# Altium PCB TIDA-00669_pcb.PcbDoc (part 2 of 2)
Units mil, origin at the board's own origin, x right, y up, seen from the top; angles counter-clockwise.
Board outline 2510.03 x 1760.03 mil, 2 copper layers (Top Layer, Bottom Layer), stack 62 mil thick; 109 components, 52 nets, 337 pads, 6 vias.
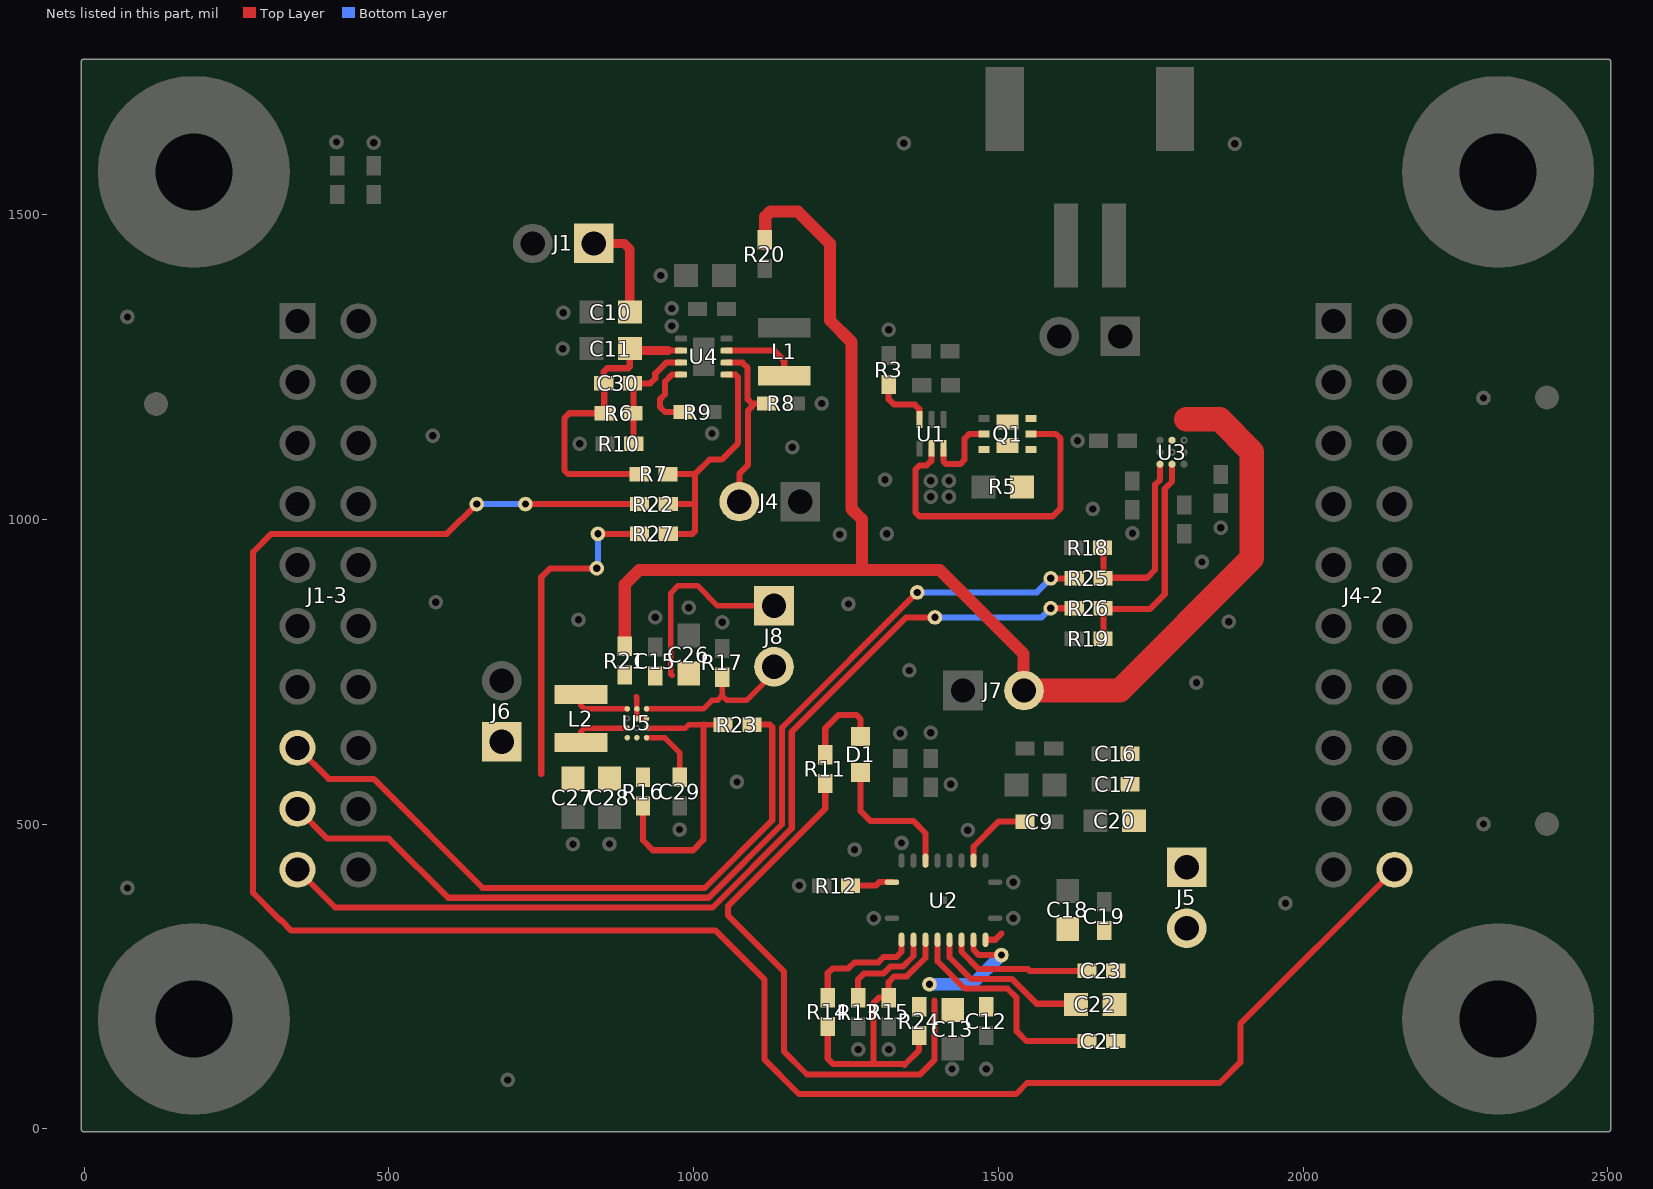
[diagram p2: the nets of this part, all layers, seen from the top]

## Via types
v1: diameter 19.68, hole 7.87, Top Layer to Bottom Layer, 6 vias

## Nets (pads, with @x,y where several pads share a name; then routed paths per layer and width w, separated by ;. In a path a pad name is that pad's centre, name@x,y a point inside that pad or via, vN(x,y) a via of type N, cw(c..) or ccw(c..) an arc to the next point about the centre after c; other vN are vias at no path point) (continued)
NetC9_1: C9.1 U2.3 | length 124.5
  Top Layer w10: U2.3@1459.21,439.96 1459.21,463 1500.15,503.94 C9.1@1543.76,503.94
NetC10_1: C10.1 C11.1 C30.1 J1.1 R6.2 R7.2 U4.2 | length 676.3
  Top Layer w10: C11.1@895.2,1280 895.2,1250.23 892.71,1247.74 858,1247.74 852.38,1242.12 C30.1@852.38,1223 853.38,1222 R6.2@853.38,1174 796,1174 788,1166 788,1080 794,1074 R7.2@910.76,1074 ; 957.7,1276.7 U4.2@979.39,1276.7
  Top Layer w15: J1.1@836.16,1452.58 886.16,1452.58 895.2,1443.54 C10.1@895.2,1340 ; C11.1@895.2,1280 898.49,1276.7 957.7,1276.7
NetC12_1: C12.1 C13.1 pad.0@1387,237 pad.0@1505,285 R11.2 R24.2 U2.18 | length 1116.8
  Top Layer w10: R11.2@1216,566.38 1216,525 1056.63,365.63 1056.63,349.63 1148,258.25 1148,127 1186,89 1371,89 1371.15,88.85 1395,112.7 1395,210 ; U2.18@1459.21,310.04 1459.21,293.79 1468,285 pad.0@1505,285
  Bottom Layer w20: pad.0@1387,237 1457,237 pad.0@1505,285
NetC15_1: C15.1 C26.1 J8.1 R21.2 U5.A2 U5.B2 U5.B3 | length 375.6
  Top Layer w9: 906,709 906.92,708.08 U5.A2@906.92,688.83 U5.B2@906.92,673.08 U5.B3@922.67,673.08 ; 964.65,744.08 962.72,746.01 962.72,879 974.72,891 1006,891 1038.92,858.08 J8.1@1131.92,858.08
NetC16_2: C16.2 C17.2 C20.2 J5.1
NetC18_2: C18.2 C19.1 C21.2 C22.2 C23.2 J5.2 U2.19 | length 30.2
  Top Layer w10: U2.19@1478.89,310.04 1495.04,310.04 1505,320
NetC21_1: C21.1 U2.15 | length 366.8
  Top Layer w10: U2.15@1400.15,310.04 1400.15,274.85 1445,230 1515,230 1530,215 1530,160 1546.06,143.94 C21.1@1645.31,143.94
NetC22_1: C22.1 U2.16 | length 268.5
  Top Layer w10: U2.16@1419.84,310.04 1419.84,281.16 1455,246 1521.63,246 1562.63,205 1626.38,205 C22.1@1627.44,203.94
NetC23_1: C23.1 U2.17 | length 238.4
  Top Layer w10: U2.17@1439.52,310.04 1439.52,290.48 1468,262 1548.25,262 1551.32,258.94 C23.1@1645.31,258.94
NetC27_1: C27.1 C28.1 J6.1 pad.0@841,919.53 pad.0@843,976 R16.1 R27.1 U5.D1 U5.D2 | length 545.3
  Top Layer w10: 750,582 750,905 764.53,919.53 pad.0@841,919.53 ; pad.0@843,976 R27.1@911,976
  Bottom Layer w10: pad.0@841,919.53 843,921.53 pad.0@843,976
NetC29_1: C29.1 U5.D3 | length 104.8
  Top Layer w9: U5.D3@922.67,641.58 952.42,641.58 976.92,617.08 C29.1@976.92,576.7
NetC30_2: C30.2 R6.1 R10.2 U4.3 | length 195.6
  Top Layer w10: C30.2@899.62,1223 929,1223 937,1231 937,1239 955,1257 U4.3@979.39,1257.02 ; R10.2@901.62,1124 C30.2@901.62,1221
NetD1_1: D1.1 R11.1 | length 141.9
  Top Layer w10: R11.1@1216,613.62 1216,657 1238,679 1267,679 1273.94,672.06 D1.1@1273.94,643.46
NetD1_2: D1.2 U2.7 | length 229.6
  Top Layer w10: D1.2@1273.94,584.41 1273.94,521.06 1290,505 1360,505 1380.47,484.53 U2.7@1380.47,439.96
NetJ1-3_17: J1-3.17 pad.0@1367,880 pad.0@1586,903 R25.2 | length 1644.8
  Top Layer w10: J1-3.17@350,525 399,476 500,476 597,379 1024.63,379 1145,499.37 1145,658 pad.0@1367,880 ; pad.0@1586,903 R25.2@1624.38,903
  Bottom Layer w10: pad.0@1367,880 1563,880 pad.0@1586,903
NetJ1-3_19: J1-3.19 pad.0@1396,839 pad.0@1586,854 R26.2 | length 1596.4
  Top Layer w10: J1-3.19@350,425 412,363 1031.25,363 1161,492.75 1161,651.37 1348.63,839 pad.0@1396,839 ; pad.0@1586,854 R26.2@1624.38,854
  Bottom Layer w10: pad.0@1396,839 1571,839 pad.0@1586,854
NetJ4_2: J4.2 R8.2 U4.6 | length 293.3
  Top Layer w10: U4.6@1054.2,1257.02 1079.98,1257.02 1088.7,1248.3 1088.7,1196.79 1095.49,1190 ; J4.2@1075,1029 1075,1075 1089,1089 1089,1178 1095.49,1184.49 1095.49,1190 ; R8.2@1120.08,1190 1095.49,1190
NetJ8_2: J8.2 R17.2 U5.A3 | length 280.4
  Top Layer w9: U5.A3@922.67,688.83 1015.83,688.83 1030,703 1039,703 1046.92,710.92 ; R17.2@1046.92,740.83 1046.92,710.92 ; J8.2@1131.92,758.08 1131.92,748.08 1086.67,702.84 1055,702.84 1046.92,710.92
NetL1_2: L1.2 U4.7 | length 126
  Top Layer w10: U4.7@1054.2,1276.7 1132.3,1276.7 1148.7,1260.3 L1.2@1148.7,1235.63
NetL2_1: L2.1 U5.A1 | length 96.3
  Top Layer w9: L2.1@815,712.37 815,694.67 820.85,688.83 U5.A1@891.17,688.83
NetL2_2: L2.2 U5.C1 | length 96.4
  Top Layer w9: L2.2@815,633.63 815,651.37 820.96,657.33 U5.C1@891.17,657.33
NetQ1_1: Q1.1 R5.2
NetQ1_2: Q1.2 U1.2 | length 534.5
  Top Layer w10: U1.2@1390,1116.38 1390,1096 1382,1088 1370.44,1088 1364,1081.56 1364,1011.44 1370.44,1005 1589,1005 1602,1018 1602,1132 1594,1140 Q1.2@1553.39,1140
NetQ1_3: Q1.3 Q1.6 Q1.7 Q1.8
NetQ1_5: Q1.5 U1.3 | length 130.6
  Top Layer w10: U1.3@1409.68,1116.38 1409.68,1095.32 1414,1091 1438,1091 1444.44,1097.44 1444.44,1132.44 1452,1140 Q1.5@1476.61,1140
NetR3_2: R3.2 U1.6 | length 98.5
  Top Layer w10: R3.2@1320,1221.38 1320,1197 1329,1188 1363,1188 1370.32,1180.68 U1.6@1370.32,1163.62
NetR7_1: R7.1 R22.1 R27.2 U4.5 | length 448.1
  Top Layer w10: R7.1@958,1074 1002,1074 ; R27.2@958.24,976 998,976 1002,980 1002,1026 ; R22.1@958.24,1025 1001,1025 1002,1026 ; U4.5@1054.2,1237.33 1068.36,1237.33 1072.7,1233 1072.7,1189.86 1073,1189.56 1073,1125 1046,1098 1026,1098 1002,1074 ; 1002,1026 1002,1074
NetR9_1: R9.1 U4.4 | length 117.7
  Top Layer w10: U4.4@979.39,1237.33 964.33,1237.33 953,1226 953,1205 945,1197 945,1184 953,1176 R9.1@983,1176
NetR12_2: R12.2 U2.10 | length 70.1
  Top Layer w10: R12.2@1257.56,398.94 1298.94,398.94 1304.52,404.52 U2.10@1325.35,404.52
NetR13_2: R13.2 U2.13 | length 163.3
  Top Layer w10: R13.2@1270,215 1270,245 1280,255 1311.78,255 1322.78,266 1343.37,266 1360.78,283.41 U2.13@1360.78,310.04
NetR14_1: R14.1 R15.2 R24.1 U2.14 | length 501
  Top Layer w10: R14.1@1220,167.76 1220,115 1228.5,106.5 1295,106.5 ; R24.1@1370,152.76 1370,129 1346,105 1344.5,106.5 1295,106.5 ; U2.14@1380.47,310.04 1380.47,280.47 1350,250 1329.41,250 1320,240.59 R15.2@1320,215 1304,215 1295,206 1295,106.5
NetR14_2: R14.2 U2.12 | length 196.2
  Top Layer w10: R14.2@1220,215 1220,256 1221,256 1228,263 1254,263 1264,273 1303,273 1312,282 1333,282 1341.1,290.1 U2.12@1341.1,310.04
NetR16_2: R16.2 R23.1 U5.C3 | length 486.2
  Top Layer w9: U5.C3@922.67,657.33 986.33,657.33 992.08,663.08 1016,663.08 R23.1@1048.3,663.08
  Top Layer w10: R16.2@916.92,529.46 916.92,473.08 933,457 999,457 1016,474 1016,663.08
PG_3.3: J1-3.15 R23.2 | length 1108.4
  Top Layer w10: J1-3.15@350,625 401,574 475,574 654,395 1018,395 1129,506 1129,659 1124.92,663.08 R23.2@1095.54,663.08
PG_5.0: J4-2.20 pad.0@644,1025 pad.0@724,1025 R22.2 | length 3501.8
  Top Layer w10: pad.0@644,1025 595,976 307,976 277,946 277,387 322,342 323,342 340,325 1036,325 1116,245 1116,113.75 1172.89,56.85 1384.4,56.85 1384.55,57 1529,57 1547,75 1863,75 1897,109 1897,172 J4-2.20@2150,425 ; pad.0@724,1025 R22.2@911,1025
  Bottom Layer w10: pad.0@644,1025 pad.0@724,1025
SCL: R18.1 R25.1 U3.A3 | length 316.2
  Top Layer w10: R18.1@1671,953 1672.62,951.38 1672.62,904 1744,904 1757,917 1757,1056.63 1765.32,1064.94 U3.A3@1765.32,1090.32
SDA: R19.1 R26.1 U3.A2 | length 378
  Top Layer w10: R19.1@1671.62,804 1672.62,805 1672.62,853 1749,853 1773,877 1773,1050 1785,1062 U3.A2@1785,1090.32
SRX: J7.2 R20.1 R21.1 U3.C2 | length 2386.2
  Top Layer w20: R21.1@886.92,791.7 886.92,893 910.68,916.76 1275,916.76 ; R20.1@1117.54,1451.04 1117.54,1496.54 1126,1505 1171,1505 1223.5,1452.5 1223.5,1326.5 1259,1291 1259,1017 1276,1000 1276,917.76 1275,916.76 ; J7.2@1542,719 1541.5,779.02 1403.76,916.76 1275,916.76
  Top Layer w40: J7.2@1542,719 1699,719 1916,936 1916,1111 1863,1164 1808,1164
pads on no net: FID1.1 FID2.1 FID3.1 H1.1 H2.1 H3.1 H4.1 H5.1 H6.1 H7.1 H8.1 HS1.0 HS2.0 HS3.0 HS4.0 J1-3.3 J1-3.5 J1-3.6 J1-3.7 J1-3.8 J1-3.10 J1-3.11 J1-3.12 J1-3.13 J1-3.14 J1-3.16 J1-3.18 J1-3.20 J2.M1 J2.M2 J4-2.1 J4-2.3 J4-2.4 J4-2.5 J4-2.6 J4-2.7 J4-2.8 J4-2.9 J4-2.10 J4-2.11 J4-2.12 J4-2.13 J4-2.14 J4-2.15 J4-2.16 J4-2.17 J4-2.18 J4-2.19 SH-J1.0 SH-J4.0 SH-J6.0 SH-J7.0 SH-J8.0 U1.1 U2.8

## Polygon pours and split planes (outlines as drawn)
GND on Bottom Layer "Ground plane" (solid, remove dead copper, pour order 2): 2475,1725 2475,25 25,25 25,1725
GND on Top Layer "Top Ground" (solid, remove dead copper, pour order 4): 2475,1725 2475,25 25,25 25,1725

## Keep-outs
Keep-Out Layer:
  lines w10: 0,0 2500,0 ; 0,0 0,1750 ; 0,0 2500,0 ; 0,1750 2500,1750 ; 0,1750 2500,1750 ; 2500,0 2500,1750 ; 2500,0 2500,1750
  text ".Layer_Name" at 577,-858.49 h60

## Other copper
Top Layer:
  rectangle net NetC18_2: 1473,303 1822,327
  rectangle net NetC5_2: 1554,359 1695.59,457
  rectangle net NetC5_2: 1475,429 1564,457
  rectangle net NetC18_2: 1685.73,127 1842,341
  rectangle net NetC16_2: 1700,480 1843,634
  rectangle net NetC16_2: 1724.88,395 1841,532.52
  rectangle net NetC5_2: 1575,429 1678,639
  rectangle net NetC18_2: 1550,296 1697,341
  rectangle net NetC7_1: 1318,522 1402,577
  rectangle net NetC7_1: 1377.14,552 1434,577
  rectangle net NetC12_1: 1354,182 1502,218
  rectangle net NetC12_1: 1371,191.56 1406.32,250
  rectangle net BAT: 1695,1123.78 1773,1333
  rectangle net SRX: 1779.1,1123 1792,1184
  rectangle net SRX: 1779.1,1144 1830,1184
  rectangle net NetC1_2: 1406,1157 1487,1238
  rectangle net GND: 1375,1024 1496,1077
  rectangle net NetQ1_3: 1497,1089 1533,1187
  rectangle net NetQ1_3: 1525,1159 1569,1187
  rectangle net NetQ1_3: 1468,1089 1508,1121
  rectangle net NetQ1_1: 1541.95,1024.46 1590,1121
  rectangle net NetC3_1: 1046.75,1290.75 1195.94,1418.68
  rectangle net NetC10_1: 872,1260 919,1361
  rectangle net GND: 948,1292.02 991,1358
  rectangle net NetC15_1: 875.11,704 1009,754.3
  rectangle net NetC27_1: 640,558 936,603
  rectangle net NetC27_1: 640,558 728,666
  rectangle net NetC27_1: 880,595 912,646
  text "TI" at 2400,991 h60 r90
  text ".CopyrightYear" at 2400,715 h60 r90
  text "©" at 2403,625 h105 r90
  text ".Layer_Name" at 577,-858.49 h60
Bottom Layer:
  text "MADE IN U.S." at 1285,1665 h60
  text "UL94V-0" at 1195,1560 h60
  text ".Layer_Name" at 577,-858.49 h60

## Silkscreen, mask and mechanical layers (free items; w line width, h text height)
Top Overlay:
  drawing of 2762 lines, arcs and shapes, not listed
  text "J1=5V CONNECT" at 745,1669 h40
  text "J4=5V ENABLE" at 737,1615 h40
  text "5V Boost" at 691,1541 h40
  text "PROT" at 1284,1424 h40
  text "40" at 2000,1405 h40
  text "20" at 2125,1405 h40
  text "1" at 305,1390 h40
  text "21" at 435,1385 h40
  text "Gauge" at 1789,1254 h40
  text "-BAT+" at 1560,1195 h40
  text ".PCB_Rev" at 150,1036 h60 r90
  text "Current" at 1206,827 h40
  text "Shunt" at 1285,777 h40
  text "Qi-RX" at 1661,680 h40
  text ".PRJ_Number" at 150,426 h60 r90
  text "COIL" at 1910,330 h40 r90
  text "10" at 295,325 h40
  text "30" at 430,325 h40
  text "31" at 2010,325 h40
  text "11" at 2135,325 h40
  text "3.3V Buck" at 707,297 h40
  text "J6=3.3V CONNECT" at 468,195 h40
  text "J8=3.3V ENABLE" at 469,137 h40
  text ".Layer_Name" at 577,-858.49 h60
Bottom Overlay:
  drawing of 2685 lines, arcs and shapes, not listed
  text ".PRJ_Number" at 148,1002 h60 r90
  text ".Layer_Name" at 577,-858.49 h60
Top Paste:
  text ".Layer_Name" at 577,-858.49 h60
Bottom Paste:
  text ".Layer_Name" at 577,-858.49 h60
Top Solder:
  text ".Layer_Name" at 577,-858.49 h60
  text ".Layer_Name" at 577,-858.49 h60
Bottom Solder:
  text ".Layer_Name" at 577,-858.49 h60
Drill Guide:
  text ".Layer_Name" at 577,-858.49 h60
M1 Board Outline:
  lines w10: 0,0 2500,0 2500,1750 0,1750 0,0
  text ".Layer_Name" at 577,-858.49 h60
M2 Board Dimensions:
  rectangle: 125,-400 500,-275
  rectangle: 0,-275 125,-150
  lines w7: 0,-275 1000,-275 ; 125,-400 125,-150 ; 250,-400 250,-150 ; 500,-400 500,-150 ; 750,-400 750,-150 ; 0,-400 0,-150 1000,-150 1000,-400 0,-400
  lines w10: -10,1751 2490,1751 ; 0,1750 0,0 2500,0 2500,1750
  text ".Layer_Name" at 577,-858.49 h60
M3 3D STEP Top:
  text ".Layer_Name" at 577,-858.49 h60
M4 3D STEP Bottom:
  text ".Layer_Name" at 577,-858.49 h60
M5 Assembly Top:
  lines w10: -292,-930.17 6308,-930.17 ; -292,-726.83 6310,-726.83 ; -292,-523.5 -292,-1133.5 3713,-1133.5 6310,-1133.5 6310,-523.5 -291.5,-523.5 -291.5,-1133.5 1284,-1133.5 ; 2173,-1133.5 2173,-523.5 ; 3440,-726.83 3440,-523.5 ; 4280,-726.83 4280,-523.5 ; 4902,-1140 4902,-937.17
  text "COMPONENTS MARKED 'DNP' SHOULD NOT BE POPULATED." at 1153.5,-318.5 h60
  text "ASSEMBLY VARIANT:" at 1153,-434 h60
  text ".VariantName" at 2189,-434 h60
  text "PCB VIEWED FROM TOP SIDE" at -228.5,-655.67 h60
  text "BOARD #:" at 2248,-655.67 h60
  text ".PRJ_Number" at 2793.5,-655.67 h60
  text "REV:" at 3638,-655.67 h60
  text ".PCB_Rev" at 3929.5,-655.67 h60
  text "SVN REV:" at 4476,-655.67 h60
  text ".VersionControl_RevNumber" at 4982,-655.67 h60
  text "PLOT NAME =" at -228.5,-1064.34 h60
  text ".plot_File_Name" at 577,-1064.34 h60
  text "GENERATED    :" at 2250,-1064.34 h60
  text ".Print_Date" at 3119.5,-1064.34 h60
  text ".Print_Time" at 3848.5,-1064.34 h60
  text "TEXAS INSTRUMENTS" at 5113,-1064.34 h60
M6 Assembly Bottom:
  lines w10: -292.5,-727.33 6309.5,-727.33 ; -290.5,-930.67 6309.5,-930.67 ; 1115.5,-1140.5 1115.5,-937.67 ; 1737.5,-727.33 1737.5,-524 ; 2577.5,-727.33 2577.5,-524 ; 3844.5,-1134 3844.5,-524 ; 4733.5,-1134 6309,-1134 6309,-524 -292.5,-524 -292.5,-1134 2304.5,-1134 6309.5,-1134 6309.5,-524
  text "COMPONENTS MARKED 'DNP' SHOULD NOT BE POPULATED." at 6102,-318 h60
  text ".VariantName" at 5058,-434 h60
  text "ASSEMBLY VARIANT:" at 6097,-434 h60
  text ".VersionControl_RevNumber" at 1035.5,-656.17 h60
  text "SVN REV:" at 1541.5,-656.17 h60
  text ".PCB_Rev" at 2088,-656.17 h60
  text "REV:" at 2379.5,-656.17 h60
  text ".PRJ_Number" at 3224,-656.17 h60
  text "BOARD #:" at 3769.5,-656.17 h60
  text "PCB VIEWED FROM BOTTOM SIDE" at 6246,-656.17 h60
  text "TEXAS INSTRUMENTS" at 904.5,-1064.84 h60
  text ".Print_Time" at 2169,-1064.84 h60
  text ".Print_Date" at 2898,-1064.84 h60
  text "GENERATED    :" at 3767.5,-1064.84 h60
  text ".plot_File_Name" at 5440.5,-1064.84 h60
  text "PLOT NAME =" at 6246,-1064.84 h60
M9 Title Sheet:
  drawing of 57 lines, arcs and shapes, not listed
  text "1" at 739.84,8036.5 h70
  text "2" at 3235.5,8036.5 h70
  text "3" at 5724.84,8036.5 h70
  text "4" at 8231.51,8036.5 h70
  text "5" at 10730.5,8036.5 h70
  text "6" at 13235.5,8036.5 h70
  text "A" at -416.5,6893.5 h70
  text "A" at 14383.5,6893.5 h70
  text "B" at -416.5,4513.5 h70
  text "B" at 14383.5,4513.5 h70
  text "C" at -416.5,2138.5 h70
  text "C" at 14383.5,2138.5 h70
  text "PROJECT TITLE:" at 11343.5,277.5 h45
  text ".PRJ_Title" at 11393.5,144.17 h70
  text "DESIGNED FOR:" at 11343.5,-23.5 h45
  text ".PRJ_Customer" at 11393.5,-163.5 h70
  text "D" at -416.5,-231.5 h70
  text "D" at 14383.5,-231.5 h70
  text "FILE NAME:" at 11343.5,-323.5 h45
  text ".PCB_File_Name_No_Path" at 11393.5,-443.5 h70
  text "Texas Instruments (TI) and/or its licensors do not warrant the accuracy or completeness of this specification" at 6374,-605.34 h45
  text "ENGINEER:" at 11343.5,-613.5 h45
  text "LAYOUT BY:" at 12848.5,-613.5 h45
  text "or any information contained therein. TI and/or its licensors do not warrant that this design will meet" at 6329.01,-718 h45
  text ".PRJ_Engineer" at 11393.5,-768.49 h70
  text ".PCB_Layout" at 12899,-768.49 h70
  text "the specifications, will be suitable for your application or fit for any particular purpose, or will operate in" at 6329.01,-830.67 h45
  text ".Layer_Name" at 577,-858.49 h60
  text "ALTIUM DESIGNER VERSION:" at 12848.5,-923.5 h45
  text "an implementation. TI and/or its licensors do not warrant that the design is production worthy. You should" at 6329.01,-943.33 h45
  text "completely validate and test your design implementation to confirm the system functionality for your application." at 6374,-1056 h45
  text ".print_Scale" at 11393.5,-1056.83 h70
  text ".Application_BuildNumber" at 12899,-1056.83 h70
  text "1" at 739.84,-1263.5 h70
  text "2" at 3235.5,-1263.5 h70
  text "3" at 5724.84,-1263.5 h70
  text "4" at 8231.51,-1263.5 h70
  text "5" at 10730.5,-1263.5 h70
  text "6" at 13235.5,-1263.5 h70
M10 Fab Notes:
  drawing of 185 lines, arcs and shapes, not listed
  text "DESIGN INFORMATION" at 12381.02,5910 h60
  text "MIN. TRACK WIDTH:" at 11736.46,5730 h60
  text "8" at 12832.7,5730 h60
  text "MIL" at 12987.46,5730 h60
  text "6" at 12825,5600 h60
  text "MIN. CLEARANCE:" at 11736.46,5598 h60
  text "MIL" at 12987.46,5598 h60
  text "MIN. VIA PAD SIZE:" at 11736.46,5466 h60
  text "10" at 12802.71,5466 h60
  text "MIL" at 12987.46,5466 h60
  text "0.05mm (2MIL)" at 12431.46,5324.29 h60
  text "MINIMUM ANNULAR RING" at 11407.23,5320 h60
  text "EXTERNAL" at 13139.46,5320 h60
  text "PER" at 11607.23,5202 h60
  text "IPC-D-275 CLASS 2 LEVEL C" at 11827.23,5202 h60
  text "MIL, HOLES" at 13315.46,5089.71 h60
  text "+/-" at 12923,5089 h60
  text "+/-" at 13777,5089 h60
  text "REGISTRATION TOLERANCES:" at 11407.23,5084 h60
  text "METAL" at 12607,5084 h60
  text "5" at 13183.2,5084 h60
  text "3" at 14016.2,5084 h60
  text "MIL" at 14132.46,5084 h60
  text "MATERIAL:" at 11332.46,4874.54 h60
  text "FR-4 High Tg" at 12318.9,4734.21 h60
  text "FR-408" at 11753.46,4725.64 h60
  text "X" at 12165.46,4725.64 h60
  text "OTHER" at 13241.46,4725.64 h60
  text "62 MIL (1.6mm) +/-10%" at 12073.56,4562.92 h60
  text "THICKNESS:" at 11407.23,4558.64 h60
  text "X" at 11945.4,4558.64 h60
  text "OTHER" at 13358.46,4558.64 h60
  text "TOLERANCE:" at 11407.23,4400.64 h60
  text "X" at 12246.53,4400.64 h60
  text "ANSI IPC-6012 TYPE 3 CLASS 2" at 12433.48,4400.64 h60
  text "OTHER +/-" at 12433.46,4244.64 h60
  text "BOW & TWIST:" at 11407.23,4087.64 h60
  text "X" at 12246.53,4087.64 h60
  text "ANSI IPC-6012 TYPE 3 CLASS 2" at 12433.48,4087.64 h60
  text "OTHER +/-" at 12433.46,3929.13 h60
  text "DRILLING:" at 11332.46,3790.64 h60
  text "REFERENCE:" at 11407.23,3673.64 h60
  text "X" at 12055.46,3673.64 h60
  text "AS SHOWN" at 12242.46,3673.64 h60
  text "X" at 12956.46,3673.64 h60
  text "NC_DRILL FILES" at 13093.46,3673.64 h60
  text "PTH MIN COPPER THICKNESS:" at 11407.23,3515.64 h60
  text "X" at 12757.46,3515.64 h60
  text "1MIL" at 12894.46,3515.64 h60
  text "OTHER" at 13391.46,3515.64 h60
  text "BOARD FINISH:" at 11332.46,3356.64 h60
  text "SILKSCREEN:" at 11487.68,3238.64 h60
  text "X" at 12436.46,3238.64 h60
  text "TOP" at 12562.46,3238.64 h60
  text "X" at 12946.46,3238.64 h60
  text "BOTTOM" at 13073.46,3238.64 h60
  text "SILKSCREEN COLOR:" at 11487.68,3071.64 h60
  text "X" at 12435.42,3071.64 h60
  text "WHITE" at 12562.46,3071.64 h60
  text "OTHER" at 13073.46,3071.64 h60
  text "SOLDER RESIST COLOR:" at 11487.68,2901.64 h60
  text "X" at 12055.42,2742.44 h60
  text "GREEN" at 12182.46,2742.44 h60
  text "BLUE" at 12773.46,2742.44 h60
  text "OTHER" at 13311.46,2742.44 h60
  text "IMMERSION GOLD (ENIG)" at 12393.46,2553.92 h60
  text "ENEPIG" at 13731,2550.64 h60
  text "SURFACE FINISH:" at 11332.46,2549.64 h60
  text "X" at 12206.51,2549.64 h60
  text "IMM. TIN/SILVER OR EQUIV" at 11662,2392.64 h60
  text "OTHER" at 13093.46,2392.64 h60
  text "ARRAY/PANEL:" at 11332.46,2213.64 h60
  text "CUT AND TRIM PER MECH LAYER 1" at 12393.46,2209.35 h60
  text "N.C. ROUTE" at 12393.46,2057.64 h60
  text "X" at 13072.46,2057.64 h60
  text "V. SCORE" at 13259.46,2057.64 h60
  text "CERTIFICATION:" at 11332.46,1920.64 h60
  text "MATERIALS AND WORKMANSHIP FOR ALL PCBS" at 12057.46,1920.64 h60
  text "TO MEET OR EXCEED THE REQUIREMENTS OF:" at 12057.46,1822.64 h60
  text "X" at 11683.96,1686.13 h60
  text "ANSI IPC-A-600F CLASS ->" at 11822.96,1686.13 h60
  text "X" at 13462.02,1686.13 h60
  text "2" at 13580.96,1686.14 h60
  text "1" at 13265.96,1684.64 h60
  text "3" at 13934.96,1684.64 h60
  text "X" at 11686.02,1526.64 h60
  text "UL 94V-0" at 11822.96,1526.64 h60
  text "X" at 12498.02,1526.64 h60
  text "RoHS" at 12634.96,1526.64 h60
  text "OTHER" at 13279.36,1526.64 h60
  text "PER ORDER" at 13676.42,1526.64 h60
  text "ADDITIONAL REQUIREMENTS:" at 11332.46,1385.64 h60
  text "MICROSECTION:" at 11407.23,1270.64 h60
  text "YES" at 12312.96,1270.64 h60
  text "REQUIRED" at 13174.46,1114.49 h60
  text "BARE BOARD ELEC. TEST:" at 11407.23,1111.64 h60
  text "NONE" at 12712.96,1111.64 h60
  text "X" at 13047.46,1111.64 h60
  text "PER ORDER" at 13766.46,1111.64 h60
  text "MANUFACTURER'S UL:" at 11407.23,954.64 h60
  text "RAIL" at 12572.96,950.35 h60
  text "METAL" at 13064.77,950.35 h60
  text "X" at 13440,950 h60
  text "SILK" at 13576.46,950.35 h60
  text ".Layer_Name" at 577,-858.49 h60
M11 Gerber Information:
  lines w10: -292,-930.17 6308,-930.17 ; -292,-726.83 6310,-726.83 ; -292,-523.5 -292,-1133.5 3713,-1133.5 6310,-1133.5 6310,-523.5 -291.5,-523.5 -291.5,-1133.5 1284,-1133.5 ; 2173,-1133.5 2173,-523.5 ; 3440,-726.83 3440,-523.5 ; 4280,-726.83 4280,-523.5 ; 4902,-1140 4902,-937.17
  text "ALL ARTWORK VIEWED FROM TOP SIDE" at -228.5,-655.67 h60
  text "BOARD #:" at 2248,-655.67 h60
  text ".PRJ_Number" at 2793.5,-655.67 h60
  text "REV:" at 3638,-655.67 h60
  text ".PCB_Rev" at 3929.5,-655.67 h60
  text "SVN REV:" at 4476,-655.67 h60
  text ".VersionControl_RevNumber" at 4982,-655.67 h60
  text "LAYER NAME =" at -228.5,-858.49 h60
  text "PLOT NAME =" at -228.5,-1064.34 h60
  text ".plot_File_Name" at 577,-1064.34 h60
  text "GENERATED    :" at 2250,-1064.34 h60
  text ".Print_Date" at 3119.5,-1064.34 h60
  text ".Print_Time" at 3848.5,-1064.34 h60
  text "TEXAS INSTRUMENTS" at 5113,-1064.34 h60
M12 Stackup:
  drawing of 191 lines, arcs and shapes, not listed
  text "Layer" at 9790.58,7830 h60
  text "Name" at 10200.49,7830 h60
  text "Material" at 11130.23,7830 h60
  text "Thickness" at 11990,7830 h60
  text "Constant" at 12639.84,7830 h60
  text "Board Layer Stack" at 13209.7,7830 h60
  text "1" at 9790.58,7710 h60
  text "Top Overlay" at 10200.49,7710 h60
  text "2" at 9790.58,7590 h60
  text "Top Solder" at 10200.49,7590 h60
  text "Solder Resist" at 11130.23,7590 h60
  text "0.40mil" at 11990,7590 h60
  text "3.5" at 12639.84,7590 h60
  text "3" at 9790.58,7470 h60
  text "Top Layer" at 10200.49,7470 h60
  text "Copper" at 11130.23,7470 h60
  text "1.40mil" at 11990,7470 h60
  text "4" at 9790.58,7350 h60
  text "Dielectric1" at 10200.49,7350 h60
  text "FR-4" at 11130.23,7350 h60
  text "59.20mil" at 11990,7350 h60
  text "4.8" at 12639.84,7350 h60
  text "5" at 9790.58,7230 h60
  text "Bottom Layer" at 10200.49,7230 h60
  text "Copper" at 11130.23,7230 h60
  text "1.40mil" at 11990,7230 h60
  text "6" at 9790.58,7110 h60
  text "Bottom Solder" at 10200.49,7110 h60
  text "Solder Resist" at 11130.23,7110 h60
  text "0.40mil" at 11990,7110 h60
  text "3.5" at 12639.84,7110 h60
  text "7" at 9790.58,6990 h60
  text "Bottom Overlay" at 10200.49,6990 h60
  text ".Layer_Name" at 577,-858.49 h60
M13 Component Bodies Top:
  text ".Layer_Name" at 577,-858.49 h60
M14 Component Bodies Bottom:
  text ".Layer_Name" at 577,-858.49 h60
M15 Courtyards Top:
  text ".Layer_Name" at 577,-858.49 h60
M16 Courtyards Bottom:
  text ".Layer_Name" at 577,-858.49 h60
Drill Drawing:
  circle w1: c5572.82,2921.77 r24.92
  lines w1: 5547.91,2448.35 5597.74,2448.35 5597.74,2498.18 5547.91,2498.18 5547.91,2448.35 ; 5547.91,2597.85 5597.74,2597.85 5597.74,2647.68 5547.91,2647.68 5547.91,2597.85 ; 5547.91,2797.18 5597.74,2797.18 5572.82,2747.35 5547.91,2797.18 ; 5547.91,3046.35 5547.91,3058.81 5560.37,3071.27 5547.91,3083.72 5547.91,3096.18 5560.37,3096.18 5572.82,3083.72 5585.28,3096.18 5597.74,3096.18 5597.74,3083.72 5585.28,3071.27 5597.74,3058.81 5597.74,3046.35 5585.28,3046.35 5572.82,3058.81 5560.37,3046.35 5547.91,3046.35 ; 5547.91,3195.85 5572.82,3208.31 5597.74,3195.85 5585.28,3220.77 5597.74,3245.68 5572.82,3233.22 5547.91,3245.68 5560.37,3220.77 5547.91,3195.85 ; 5557.88,2458.32 5587.77,2458.32 5587.77,2488.22 5557.88,2488.22 5557.88,2458.32
  lines w12: 5480,2403.5 7598.44,2403.5 ; 5480,3300.5 7598.44,3300.5 ; 5850.51,2254 5850.51,3450 ; 6207.67,2254 6207.67,3450 ; 6869.15,2254 6869.15,3450 ; 7153.35,2254 7153.35,3450 ; 5480,2254 7598.44,2254 7598.44,3450 5480,3450 5480,2254
  text "Symbol" at 5569.7,3345.35 h72
  text "Quantity" at 5895.36,3345.35 h72
  text "Finished Hole Size" at 6252.52,3345.35 h72
  text "Plated" at 6914,3345.35 h72
  text "Hole Type" at 7198.2,3345.35 h72
  text "4" at 5895.36,3195.85 h60
  text "4.00mil (0.102mm)" at 6252.52,3195.85 h60
  text "PTH" at 6914,3195.85 h60
  text "Round" at 7198.2,3195.85 h60
  text "6" at 5895.36,3046.35 h60
  text "7.87mil (0.200mm)" at 6252.52,3046.35 h60
  text "PTH" at 6914,3046.35 h60
  text "Round" at 7198.2,3046.35 h60
  text "70" at 5895.36,2896.85 h60
  text "12.00mil (0.305mm)" at 6252.52,2896.85 h60
  text "PTH" at 6914,2896.85 h60
  text "Round" at 7198.2,2896.85 h60
  text "40" at 5895.36,2747.35 h60
  text "39.37mil (1.000mm)" at 6252.52,2747.35 h60
  text "PTH" at 6914,2747.35 h60
  text "Round" at 7198.2,2747.35 h60
  text "14" at 5895.36,2597.85 h60
  text "40.00mil (1.016mm)" at 6252.52,2597.85 h60
  text "PTH" at 6914,2597.85 h60
  text "Round" at 7198.2,2597.85 h60
  text "8" at 5895.36,2448.35 h60
  text "125.98mil (3.200mm)" at 6252.52,2448.35 h60
  text "PTH" at 6914,2448.35 h60
  text "Round" at 7198.2,2448.35 h60
  text "142 Total" at 5895.36,2298.85 h60
  text ".Layer_Name" at 577,-858.49 h60

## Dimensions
0,1750 to 0,0 on M2 Board Dimensions
0,0 to 2500,0 on M2 Board Dimensions
0,-400 to 1000,-400 on M2 Board Dimensions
